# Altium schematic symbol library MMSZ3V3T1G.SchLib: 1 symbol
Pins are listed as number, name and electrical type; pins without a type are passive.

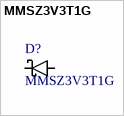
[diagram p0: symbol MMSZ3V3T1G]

## MMSZ3V3T1G
designator D?
Zener Diode 3.3 V 500 mW Â±5% Surface Mount SOD-123; MF: ON Semiconductor
footprint *MMSZ5V6T1G_MMSZ3V3T1G(Primary)
pins: A, K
